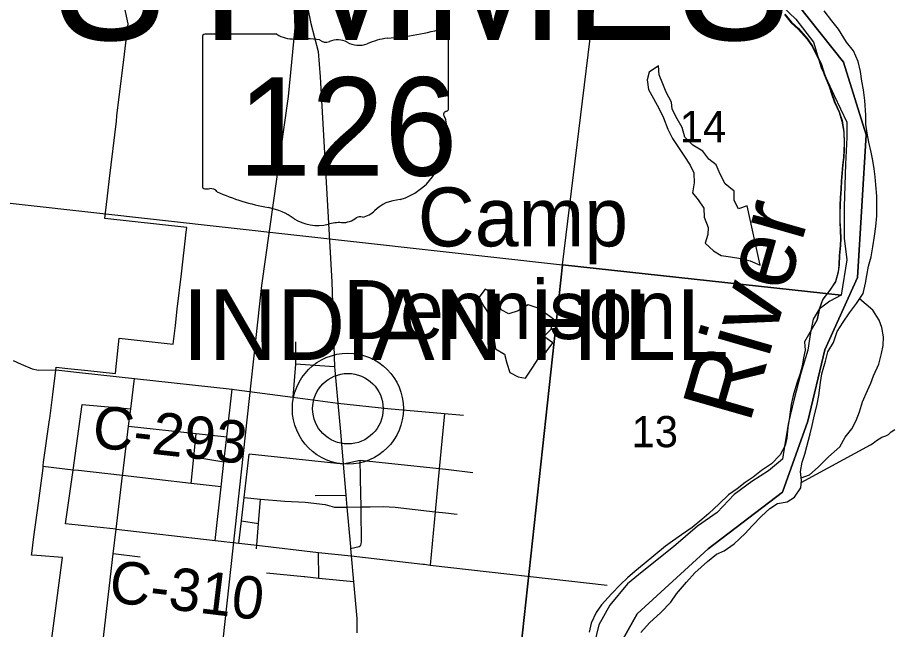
# Model space of a CAD drawing. Extents: x 44.2 to 78.2, y 4.5 to 26.5.
# Drawn here: x 49.189 to 50.361, y 23.234 to 24.054 of the extents above; entities that cross this region are included whole.
import ezdxf

# ---------------------------------------------------------------- set-up
doc = ezdxf.new("R2010")
doc.units = 0
for name, color, linetype in [('GM_X_City_Street', 7, 'Continuous'), ('GM_X_Corporation_Text', 7, 'Continuous'), ('GM_X_County_Road', 7, 'Continuous'), ('GM_X_County_Road_Text', 7, 'Continuous'), ('GM_X_Interstate_Route', 7, 'Continuous'), ('GM_X_Major_River', 7, 'Continuous'), ('GM_X_Major_River_Text', 7, 'Continuous'), ('GM_X_Minor_Lake', 7, 'Continuous'), ('GM_X_Minor_River', 7, 'Continuous'), ('GM_X_Rail_Line', 7, 'Continuous'), ('GM_X_Section', 7, 'Continuous'), ('GM_X_Section_Text', 7, 'Continuous'), ('GM_X_State_Location', 7, 'Continuous'), ('GM_X_State_Route', 7, 'Continuous'), ('GM_X_State_Shield', 7, 'Continuous'), ('GM_X_Township_Road', 7, 'Continuous'), ('GM_X_Township_Text', 7, 'Continuous'), ('GM_X_Unincorporated', 7, 'Continuous'), ('GM_X_Unincorporated_Location', 7, 'Continuous'), ('GM_X_Unincorporated_Text', 7, 'Continuous'), ('SH_Cut_Line', 7, 'Continuous')]:
    doc.layers.add(name, color=color, linetype=linetype)

msp = doc.modelspace()

# ---------------------------------------------------------------- linework, layer by layer
at = {"layer": 'GM_X_City_Street'}
msp.add_lwpolyline([(49.183, 23.5943), (49.1936, 23.5894), (49.2082, 23.5834), (49.2169, 23.5816), (49.24, 23.5818), (49.2756, 23.5779)], dxfattribs=at)
at = {"layer": 'GM_X_County_Road'}
for points in [[(49.2689, 22.9223), (49.2965, 23.1616), (49.3169, 23.3355), (49.3208, 23.3684), (49.3292, 23.4402), (49.3295, 23.4424), (49.3374, 23.5063), (49.3403, 23.5298), (49.3454, 23.5703)], [(49.2756, 23.5779), (49.3454, 23.5703), (49.476, 23.556), (49.4789, 23.5557), (49.5572, 23.5453), (49.6178, 23.5372)], [(49.3208, 23.3684), (49.4532, 23.3532), (49.4852, 23.3495), (49.509, 23.3468), (49.5917, 23.3372), (49.6357, 23.3326), (49.7317, 23.3216)], [(49.7317, 23.3216), (49.7337, 23.3214), (49.7411, 23.3203), (49.9786, 23.2935)]]:
    msp.add_lwpolyline(points, dxfattribs=at)
at = {"layer": 'GM_X_Interstate_Route'}
msp.add_lwpolyline([(49.2315, 23.1982), (49.2488, 23.3306), (49.2146, 23.3333), (49.2073, 23.3338), (49.2076, 23.336), (49.2105, 23.3582), (49.2166, 23.4034), (49.2228, 23.4502), (49.2231, 23.4537), (49.2236, 23.4583), (49.2314, 23.5149), (49.2317, 23.5167), (49.2359, 23.549), (49.24, 23.5814), (49.2405, 23.5856), (49.2562, 23.5839), (49.2827, 23.5811), (49.2828, 23.5811), (49.3198, 23.577), (49.3203, 23.5822), (49.3248, 23.6245), (49.3973, 23.6164), (49.4001, 23.6415), (49.4026, 23.6634), (49.4081, 23.7107), (49.4145, 23.7665), (49.4152, 23.7727), (49.3054, 23.7849), (49.3085, 23.8112), (49.3118, 23.8385), (49.321, 23.9154), (49.3218, 23.9223), (49.3317, 24.0048), (49.3326, 24.0126), (49.3366, 24.0458), (49.3248, 24.102)], dxfattribs=at)
at = {"layer": 'GM_X_Major_River'}
for points in [[(50.0504, 23.2569), (50.0636, 23.2707), (50.0714, 23.2819), (50.0847, 23.2976), (50.0959, 23.3099), (50.1126, 23.3252), (50.1246, 23.3348), (50.1353, 23.3395), (50.1484, 23.3488), (50.1631, 23.3625), (50.1725, 23.373), (50.1849, 23.386), (50.1961, 23.3961), (50.2065, 23.4027), (50.2195, 23.4051), (50.2291, 23.4114), (50.2377, 23.4237), (50.2387, 23.4336), (50.2374, 23.4458), (50.2396, 23.4583), (50.2433, 23.4689), (50.2458, 23.4791), (50.2503, 23.4961), (50.2528, 23.5074), (50.2553, 23.5177), (50.2595, 23.5362), (50.2617, 23.5476), (50.2643, 23.565), (50.2661, 23.5767), (50.2706, 23.5934), (50.274, 23.6059), (50.2814, 23.6186), (50.2863, 23.6334), (50.2946, 23.6457), (50.3028, 23.6585), (50.3122, 23.6708), (50.3212, 23.6843), (50.3246, 23.6983), (50.3263, 23.7082), (50.3285, 23.7207), (50.3318, 23.7336), (50.334, 23.7468), (50.3366, 23.7612), (50.3384, 23.7741), (50.3394, 23.7885), (50.3397, 23.7992), (50.3396, 23.8148), (50.3381, 23.83), (50.3375, 23.8407), (50.3359, 23.8513), (50.3342, 23.8624), (50.3322, 23.8739), (50.3287, 23.8869), (50.3267, 23.8991), (50.325, 23.9113), (50.3249, 23.9231), (50.3234, 23.9429), (50.3215, 23.957), (50.3195, 23.9688), (50.3178, 23.9818), (50.3147, 23.9951), (50.3082, 24.0093), (50.299, 24.0209), (50.2883, 24.0387), (50.2795, 24.0499), (50.2691, 24.063)], [(50.2159, 24.058), (50.2247, 24.0472), (50.2344, 24.0386), (50.2463, 24.0251), (50.2533, 24.015), (50.2587, 24.0035), (50.2653, 23.9905), (50.2692, 23.9778), (50.2756, 23.9617), (50.2788, 23.9518), (50.2824, 23.9414), (50.2889, 23.9272), (50.2929, 23.9154), (50.2952, 23.9005), (50.2956, 23.8856), (50.2954, 23.8761), (50.2948, 23.8666), (50.2938, 23.8564), (50.2928, 23.8454), (50.2919, 23.8348), (50.2912, 23.8241), (50.2906, 23.8124), (50.29, 23.8021), (50.2898, 23.7915), (50.2899, 23.7808), (50.2904, 23.7683), (50.2909, 23.758), (50.2903, 23.7481), (50.2893, 23.7352), (50.2886, 23.7223), (50.2877, 23.7128), (50.284, 23.6999), (50.2761, 23.6883), (50.2667, 23.676), (50.2623, 23.6635), (50.2593, 23.6484), (50.2429, 23.6193)], [(50.2162, 24.0586), (50.2251, 24.0478), (50.2348, 24.0392), (50.2466, 24.0257), (50.2536, 24.0156), (50.259, 24.0041), (50.2656, 23.991), (50.2695, 23.9784), (50.276, 23.9623), (50.2792, 23.9524), (50.2827, 23.942), (50.2893, 23.9278), (50.2932, 23.9159), (50.2955, 23.9011), (50.2959, 23.8862), (50.2957, 23.8767), (50.2952, 23.8672), (50.2942, 23.857), (50.2932, 23.846), (50.2922, 23.8354), (50.2916, 23.8247), (50.2909, 23.8129), (50.2903, 23.8027), (50.2901, 23.792), (50.2902, 23.7814), (50.2907, 23.7688), (50.2913, 23.7586), (50.2907, 23.7487), (50.2896, 23.7358), (50.289, 23.7229), (50.288, 23.7134), (50.2843, 23.7005), (50.2765, 23.6889), (50.2671, 23.6766), (50.2626, 23.6641), (50.2596, 23.6489), (50.2429, 23.6193)], [(50.2429, 23.6193), (50.2436, 23.6084), (50.2415, 23.5982), (50.2394, 23.5868), (50.2369, 23.577), (50.2324, 23.5641), (50.2275, 23.5475), (50.225, 23.5354), (50.2236, 23.5259), (50.2223, 23.5153), (50.2205, 23.5047), (50.2191, 23.4906), (50.2169, 23.4808), (50.2102, 23.468), (50.1986, 23.4561), (50.1851, 23.4469), (50.1739, 23.438), (50.1631, 23.431), (50.1523, 23.4224), (50.1411, 23.4143), (50.1283, 23.4024), (50.1147, 23.3894), (50.1051, 23.3812), (50.0923, 23.3705), (50.0781, 23.3609), (50.0661, 23.3524), (50.0565, 23.3457), (50.041, 23.3327), (50.0279, 23.322), (50.0155, 23.3116), (50.0058, 23.3034), (49.9961, 23.2945), (49.9841, 23.2818), (49.9709, 23.2669), (49.9638, 23.2568), (49.957, 23.2425), (49.9541, 23.2304)], [(50.0236, 23.2301), (50.0349, 23.2431), (50.0504, 23.2569)]]:
    msp.add_lwpolyline(points, dxfattribs=at)
at = {"layer": 'GM_X_Minor_Lake'}
for p, q in [((50.1833, 23.7224), (50.1659, 23.8018)), ((49.8219, 23.6533), (49.8289, 23.6102))]:
    msp.add_line(p, q, dxfattribs=at)
for points in [[(50.1659, 23.8018), (50.1544, 23.7978), (50.1486, 23.809), (50.1485, 23.8215), (50.1365, 23.8313), (50.1296, 23.8444), (50.1245, 23.8566), (50.1144, 23.8641), (50.1063, 23.8749), (50.0932, 23.8831), (50.0824, 23.894), (50.0788, 23.9066), (50.0723, 23.9185), (50.0653, 23.9312), (50.0647, 23.9407), (50.0574, 23.9542), (50.0531, 23.9653), (50.048, 23.9772), (50.0471, 23.9894), (50.0348, 23.9809), (50.0319, 23.9707), (50.0336, 23.9578), (50.0405, 23.9458), (50.0482, 23.9316), (50.0537, 23.9197), (50.0598, 23.9044), (50.066, 23.8921), (50.0722, 23.8824), (50.0811, 23.8693), (50.0896, 23.8562), (50.0943, 23.8462), (50.0948, 23.8326), (50.0926, 23.8193), (50.1003, 23.8096), (50.1077, 23.7988), (50.1082, 23.7867), (50.1136, 23.7729), (50.1134, 23.7634), (50.1098, 23.7517), (50.1209, 23.7415), (50.1311, 23.7352), (50.1436, 23.7335), (50.1572, 23.7313), (50.1701, 23.728), (50.1833, 23.7224)], [(49.8289, 23.6102), (49.8409, 23.6031), (49.8441, 23.5909), (49.848, 23.5782), (49.8593, 23.5727), (49.8691, 23.571), (49.8786, 23.5856), (49.886, 23.5968), (49.8969, 23.6061), (49.9055, 23.6181), (49.8935, 23.6267), (49.9032, 23.6367), (49.9065, 23.65), (49.8968, 23.657), (49.8848, 23.6649), (49.8724, 23.6693), (49.8593, 23.6612), (49.8466, 23.6569), (49.8365, 23.6625), (49.8329, 23.6728), (49.8256, 23.6844), (49.815, 23.6899), (49.8064, 23.6787), (49.8138, 23.6664), (49.8219, 23.6533)]]:
    msp.add_lwpolyline(points, dxfattribs=at)
at = {"layer": 'GM_X_Minor_River'}
for points in [[(50.2382, 23.4373), (50.2494, 23.4414), (50.261, 23.4515), (50.275, 23.4653), (50.2901, 23.479), (50.2972, 23.4918), (50.3061, 23.5027), (50.3121, 23.5143), (50.3165, 23.5257), (50.3205, 23.5389), (50.3269, 23.5543), (50.3317, 23.5641), (50.3353, 23.574), (50.3421, 23.5898), (50.3458, 23.6038), (50.3479, 23.6144), (50.3485, 23.6262), (50.3461, 23.6387), (50.3429, 23.6487), (50.3341, 23.6618), (50.3163, 23.6771)], [(50.2384, 23.4309), (50.3311, 23.4817), (50.3346, 23.4835), (50.3392, 23.4872), (50.3462, 23.4919), (50.3516, 23.4937), (50.355, 23.4955), (50.3589, 23.4988), (50.3635, 23.5021)]]:
    msp.add_lwpolyline(points, dxfattribs=at)
at = {"layer": 'GM_X_Rail_Line'}
for points in [[(49.1046, 24.3116), (49.2515, 24.3412), (49.3807, 24.3917), (49.4119, 24.4102), (49.4376, 24.4247), (49.6058, 24.5433), (49.6698, 24.573), (49.8047, 24.5934), (49.9035, 24.5664), (49.9986, 24.4763), (50.0826, 24.2859), (50.2187, 24.0909), (50.2948, 23.9944), (50.3252, 23.8967), (50.3138, 23.7059), (50.2701, 23.6086), (50.2473, 23.5132), (50.2134, 23.4182), (50.1138, 23.3419), (50.0184, 23.2552), (49.9104, 23.0622)], [(49.9104, 23.0622), (50.0184, 23.2552), (50.1138, 23.3419), (50.2134, 23.4182), (50.2473, 23.5132), (50.2701, 23.6086), (50.3138, 23.7059), (50.3252, 23.8967), (50.2948, 23.9944), (50.2187, 24.0909), (50.0826, 24.2859), (49.9986, 24.4763), (49.9035, 24.5664), (49.8047, 24.5934), (49.6698, 24.573), (49.6058, 24.5433), (49.4376, 24.4247), (49.4119, 24.4102), (49.3807, 24.3917), (49.2515, 24.3412), (49.1046, 24.3116)], [(49.3823, 22.417), (49.4335, 22.9419), (49.5157, 23.6948), (49.5516, 23.9481), (49.5607, 24.0404), (49.5582, 24.101), (49.5479, 24.1577), (49.5234, 24.2196), (49.4858, 24.2792), (49.3949, 24.3999)]]:
    msp.add_lwpolyline(points, dxfattribs=at)
at = {"layer": 'GM_X_Section'}
for points in [[(50.0124, 24.3902), (50.0159, 24.3697), (50.0312, 24.3372), (50.0483, 24.2979), (50.0722, 24.257), (50.1166, 24.1972), (50.1576, 24.134), (50.1952, 24.0862), (50.231, 24.052), (50.2549, 24.0213), (50.2652, 23.9871), (50.2823, 23.9496), (50.2993, 23.9137), (50.2993, 23.8932), (50.2976, 23.8574), (50.2959, 23.801), (50.2959, 23.7583), (50.2993, 23.7293), (50.2916, 23.682), (49.9184, 23.7227), (50.0064, 24.4433)], [(48.7465, 23.8538), (49.9184, 23.7227), (49.8403, 23.0036), (49.8372, 23.0006), (49.8007, 22.9753), (49.7648, 22.9454), (49.7332, 22.9224), (49.7059, 22.8985), (49.6863, 22.8746), (49.6675, 22.8353), (49.647, 22.7909), (49.6359, 22.761), (49.6394, 22.7393), (49.6374, 22.7347), (48.6514, 22.8354)]]:
    msp.add_lwpolyline(points, close=True, dxfattribs=at)
msp.add_lwpolyline([(49.8403, 23.0036), (49.9184, 23.7227), (50.2916, 23.682), (50.2768, 23.6742), (50.2622, 23.6635), (50.2544, 23.6497), (50.2506, 23.632), (50.2471, 23.6085), (50.2378, 23.5773), (50.2283, 23.5415), (50.2213, 23.5113), (50.2162, 23.4823), (50.2131, 23.4623), (50.1946, 23.4467), (50.1723, 23.4324), (50.1485, 23.4151), (50.1257, 23.3909), (50.0992, 23.3725), (50.0672, 23.3448), (50.0252, 23.3115), (50.0056, 23.2953), (49.9819, 23.2666), (49.967, 23.2404), (49.9608, 23.2144)], dxfattribs=at)
at = {"layer": 'GM_X_State_Route'}
msp.add_lwpolyline([(49.572, 24.0924), (49.5816, 24.0463), (49.5912, 24.0086), (49.5942, 23.9746), (49.6098, 23.7), (49.6133, 23.586), (49.6134, 23.5815), (49.6178, 23.5372), (49.621, 23.499), (49.6248, 23.4555), (49.6285, 23.4139), (49.6299, 23.3981), (49.6347, 23.3447), (49.6348, 23.3425), (49.6357, 23.3326), (49.6388, 23.2979), (49.6431, 23.2489), (49.6429, 23.2295)], dxfattribs=at)
at = {"layer": 'GM_X_State_Shield'}
for p, q in [((49.4363, 24.0282), (49.4363, 23.8281)), ((49.5361, 24.0316), (49.4396, 24.0316)), ((49.7659, 23.9319), (49.7659, 24.0366)), ((49.7659, 23.9319), (49.7659, 23.9319))]:
    msp.add_line(p, q, dxfattribs=at)
for centre, major_axis, start_param, end_param in [((49.6485, 24.3045), (0.3495, 0), 4.814394, 5.042369), ((49.7622, 24.037), (0.00367, 0), 6.141152, 7.989035), ((49.4401, 24.0286), (0.00382, 0), 1.712693, 3.28349), ((49.5591, 24.0549), (0.037, 0), 4.042523, 4.731795), ((49.5713, 23.9193), (0.133, 0), 1.404758, 1.657858), ((49.6172, 24.0065), (0.0222, 0), 0.950623, 2.079405), ((49.6931, 23.9705), (0.0703, 0), 1.699011, 2.107814), ((49.6015, 24.0297), (0.0107, 0), 3.836095, 5.185415), ((49.6459, 24.0383), (0.0267, 0), 4.081561, 5.145723), ((49.762, 23.9315), (0.00393, 0), 5.05454, 6.418171), ((49.765, 23.9242), (0.00568, 0), 1.883978, 3.671073), ((49.7289, 23.911), (0.0341, 0), 5.934695, 6.695948), ((49.779, 23.8881), (0.0248, 0), 2.387724, 3.262537), ((49.6681, 23.8748), (0.0874, 0), 5.101752, 6.440018), ((49.4401, 23.8276), (0.00385, 0), 3.00124, 4.508301), ((49.4407, 23.8481), (0.0294, 0), 4.665946, 4.897461), ((49.4467, 23.8165), (0.0106, 0), 0.519207, 1.627899), ((49.5805, 23.9963), (0.2524, 0), 4.195997, 4.488961), ((49.7049, 23.7719), (0.0479, 0), 1.647645, 2.488434), ((49.5053, 23.7382), (0.079, 0), 0.823519, 1.323587), ((49.6443, 23.8087), (0.0282, 0), 4.937069, 5.64225), ((49.5907, 23.8155), (0.0501, 0), 4.026481, 4.996735), ((49.6197, 23.7463), (0.0412, 0), 1.495662, 1.94098), ((49.6233, 23.8006), (0.0267, 0), 4.691044, 5.507374), ((49.6475, 23.7812), (0.00752, 0), 1.147584, 2.315152)]:
    msp.add_ellipse(centre, major_axis=major_axis, ratio=0.8, start_param=start_param, end_param=end_param, dxfattribs=at)
at = {"layer": 'GM_X_Township_Road'}
for p, q in [((49.561, 23.6193), (49.561, 23.5894)), ((49.561, 23.5894), (49.5572, 23.5453)), ((49.6133, 23.586), (49.561, 23.5894)), ((49.2753, 23.5357), (49.3403, 23.5298)), ((49.465, 23.4582), (49.4248, 23.4649)), ((49.6248, 23.4555), (49.4987, 23.4689)), ((49.2631, 23.4477), (49.2223, 23.4523)), ((49.7983, 23.4439), (49.7624, 23.4482)), ((49.5871, 23.4134), (49.6285, 23.4139)), ((49.7578, 23.3908), (49.7775, 23.3886)), ((49.3208, 23.3684), (49.253, 23.3755)), ((49.4886, 23.3795), (49.5115, 23.3762)), ((49.3528, 23.3308), (49.3169, 23.3355)), ((49.5921, 23.3025), (49.5917, 23.3372))]:
    msp.add_line(p, q, dxfattribs=at)
for points in [[(49.4532, 23.3532), (49.4613, 23.4253), (49.465, 23.4582), (49.4688, 23.4924), (49.476, 23.556)], [(49.253, 23.3755), (49.2631, 23.4477), (49.2753, 23.5357)], [(49.6178, 23.5372), (49.684, 23.53), (49.7605, 23.5236), (49.7859, 23.5214)], [(49.7605, 23.5236), (49.7534, 23.4493), (49.748, 23.3919), (49.7411, 23.3203)], [(49.3374, 23.5063), (49.428, 23.4967), (49.4688, 23.4924)], [(49.4214, 23.4298), (49.4248, 23.4649), (49.428, 23.4967)], [(49.4852, 23.3495), (49.4886, 23.3795), (49.4921, 23.4108), (49.4987, 23.4689)], [(49.7624, 23.4482), (49.7534, 23.4493), (49.6476, 23.4607), (49.6248, 23.4555)], [(49.648, 23.4355), (49.648, 23.4392), (49.6476, 23.4607)], [(49.4613, 23.4253), (49.4214, 23.4298), (49.3292, 23.4402), (49.2701, 23.4469), (49.2631, 23.4477)], [(49.6489, 23.3889), (49.6487, 23.3963), (49.6487, 23.3983), (49.648, 23.4355)], [(49.4921, 23.4108), (49.5142, 23.4088), (49.5468, 23.4058), (49.5741, 23.4047), (49.6006, 23.4014), (49.613, 23.398), (49.6299, 23.3981), (49.6487, 23.3983), (49.6609, 23.3983), (49.6783, 23.399), (49.6946, 23.3979), (49.748, 23.3919), (49.7578, 23.3908)], [(49.5086, 23.3423), (49.5088, 23.3436), (49.509, 23.3468), (49.5115, 23.3762), (49.5142, 23.4088)], [(49.6492, 23.3702), (49.6491, 23.3749), (49.6489, 23.3889)], [(49.6493, 23.3516), (49.6495, 23.3534), (49.6492, 23.3702)], [(49.6348, 23.3425), (49.6462, 23.3454), (49.6475, 23.3462), (49.6484, 23.3472), (49.649, 23.3489), (49.6493, 23.3516)], [(49.5733, 23.3044), (49.5724, 23.3045), (49.5223, 23.3094)], [(49.6388, 23.2979), (49.5921, 23.3025), (49.5733, 23.3044)]]:
    msp.add_lwpolyline(points, dxfattribs=at)
at = {"layer": 'GM_X_Unincorporated'}
for radius in [0.0744, 0.0472]:
    msp.add_circle((49.6311, 23.5299), radius, dxfattribs=at)
at = {"layer": 'GM_X_Unincorporated_Location'}
msp.add_line((49.6311, 23.5299), (49.6311, 23.5299), dxfattribs=at)
at = {"layer": 'SH_Cut_Line'}
for points in [[(49.9104, 23.0622), (50.0184, 23.2552), (50.1138, 23.3419), (50.2134, 23.4182), (50.2473, 23.5132), (50.2701, 23.6086), (50.3138, 23.7059), (50.3252, 23.8967), (50.2948, 23.9944), (50.2187, 24.0909), (50.0826, 24.2859), (49.9986, 24.4763), (49.9035, 24.5664), (49.8047, 24.5934), (49.6698, 24.573), (49.6058, 24.5433), (49.4376, 24.4247), (49.4119, 24.4102), (49.3807, 24.3917), (49.2515, 24.3412), (49.1046, 24.3116)], [(49.1046, 24.3116), (49.2515, 24.3412), (49.3807, 24.3917), (49.4119, 24.4102), (49.4376, 24.4247), (49.6058, 24.5433), (49.6698, 24.573), (49.8047, 24.5934), (49.9035, 24.5664), (49.9986, 24.4763), (50.0826, 24.2859), (50.2187, 24.0909), (50.2948, 23.9944), (50.3252, 23.8967), (50.3138, 23.7059), (50.2701, 23.6086), (50.2473, 23.5132), (50.2134, 23.4182), (50.1138, 23.3419), (50.0184, 23.2552), (49.9104, 23.0622)]]:
    msp.add_lwpolyline(points, dxfattribs=at)

# ---------------------------------------------------------------- texts
at = {"layer": 'GM_X_Corporation_Text'}
msp.add_text('INDIAN HILL', height=0.094697, rotation=0, dxfattribs=at).set_placement((49.4095, 23.5953))
at = {"layer": 'GM_X_County_Road_Text'}
for s, rotation, p in [('C-293', 353.6602, (49.2871, 23.4785)), ('C-310', 353.1208, (49.3095, 23.2711))]:
    msp.add_text(s, height=0.05682, rotation=rotation, dxfattribs=at).set_placement(p)
at = {"layer": 'GM_X_Major_River_Text'}
msp.add_text('River', height=0.09468, rotation=74.001, dxfattribs=at).set_placement((50.1689, 23.508))
at = {"layer": 'GM_X_Section_Text'}
for s, p in [('14', (50.0755, 23.887)), ('13', (50.011, 23.4783))]:
    msp.add_text(s, height=0.04186, rotation=0, dxfattribs=at).set_placement(p)
at = {"layer": 'GM_X_State_Location'}
for s in ['s', 'r']:
    msp.add_text(s, height=0.000189, dxfattribs=at).set_placement((49.5974, 23.9148))
msp.add_text('126', height=0.000189, rotation=0, dxfattribs=at).set_placement((49.5305, 23.9011))
at = {"layer": 'GM_X_State_Shield'}
msp.add_text('126', height=0.13184, dxfattribs=at).set_placement((49.4837, 23.8422))
at = {"layer": 'GM_X_Township_Text'}
msp.add_text('SYMMES', height=0.17045, rotation=0, dxfattribs=at).set_placement((49.2364, 24.0241))
at = {"layer": 'GM_X_Unincorporated_Text'}
for s, p in [('Camp', (49.7247, 23.7474)), ('Dennison', (49.6247, 23.6232))]:
    msp.add_text(s, height=0.07898, rotation=0, dxfattribs=at).set_placement(p)

doc.saveas('drawing.dxf')
